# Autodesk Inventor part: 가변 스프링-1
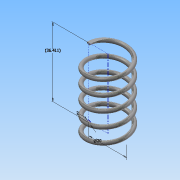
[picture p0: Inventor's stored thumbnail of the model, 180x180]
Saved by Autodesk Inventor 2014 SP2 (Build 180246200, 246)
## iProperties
Created: 2016-01
Part Number: 가변 스프링-1
Material: 스테인레스 스틸
Document SubType Name: Modeling
Designer: Administrator
Density: 8.08 g/cm^3
Appearance: 반연마
Mass: 7.88162 g
Surface Area: 19.7619 cm^2
Volume: 0.975448 cm^3
Author: Administrator
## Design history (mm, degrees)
sketch "스케치2"
  geometry: L1 (0, 0)-(10, 0); L2 (10, 0)-(10, 36.411); L3 (10, 36.411)-(0, 36.411); L4 (0, 36.411)-(0, 0); C1 r 1 at (10, 0)
  constraints: 8 end point, 2 parallel, 1 centre point, 1 coincident, 1 horizontal, 1 perpendicular
  dimensions: "d0" = 2 diameter of C1; "d1" = 20 diameter of L2 L4; "d2" = 36.4112 distance between parallel lines of L3 L1 (derived)
feature "코일1" pitch "d3" = 10; turns "d5" = 5; dims "d4" = 36.4112 (= d2), "d6" = 0, angle "d7" = 90 deg, angle "d8" = 90 deg, "d9" = 0, "d10" = 0
sketch "스케치3"
  geometry: L1 (-11, 0)-(-9, 0) reference; 1 further point
  constraints: 1 horizontal alignment
extrude "돌출1" cut sketch "스케치3" stored distance "d11" = 10; taper "d12" = 0 deg
node "작업 평면1"
sketch "스케치4"
  geometry: L1 (1, 0)-(-1, 0) reference; 1 further point
  constraints: 1 horizontal alignment
extrude "돌출2" cut sketch "스케치4" stored distance "d14" = 10; taper "d15" = 0 deg
node "솔리드1"
node "절단 모서리 투영1"
node "절단 모서리 투영2"
other parameters: "d13" = 0
